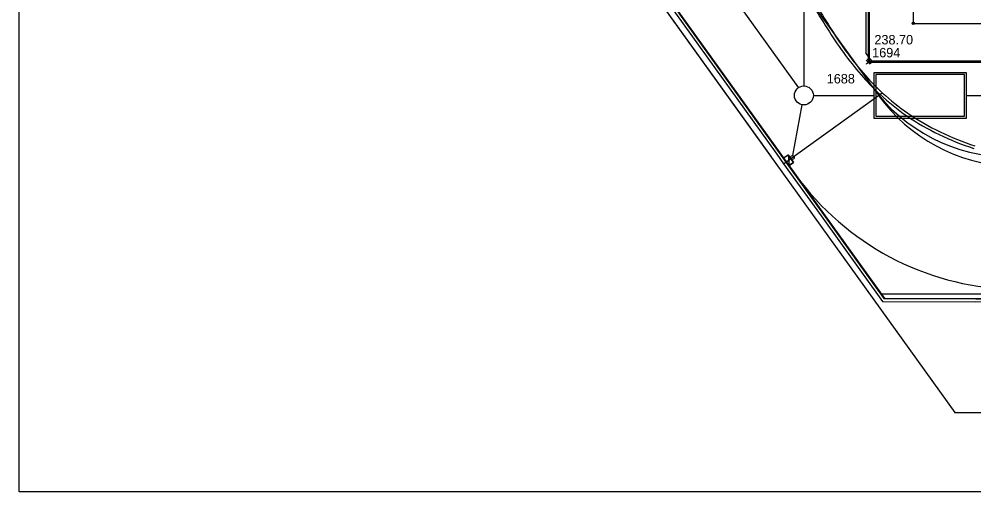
# Model space of a CAD drawing. Extents: x -264165 to -263733, y -1242319 to -1242245.
# Drawn here: x -264165.4 to -264114.9, y -1242319.2 to -1242294.2 of the extents above; entities that cross this region are included whole.
import ezdxf

# ---------------------------------------------------------------- set-up
doc = ezdxf.new("R2010")
doc.units = 0
for name, color, linetype in [('KFA_BOD_CISLO', 7, 'Continuous'), ('KFA_BOD_SYMBOL', 7, 'Continuous'), ('KFA_BOD_VYSKA', 7, 'Continuous'), ('KFA_SO_20-2_OBRUBNIKY_HORNA_HRANA', 7, 'Continuous'), ('PROJEKT_OBRUBNIKY_KOMUNIKACIE', 7, 'Continuous'), ('PROJEKT_TDZ_VODOROVNE', 7, 'Continuous'), ('RAM_NA_TLAC_1-250', 7, 'Continuous'), ('ROZHRANIE_SO_20-3_a_20-1', 7, 'Continuous'), ('SITUACIA_DSP_2D', 7, 'Continuous'), ('SO_20-1_OBRUBNIKY_DOLNA_HRANA', 7, 'Continuous'), ('SO_20-1_OBRUBNIKY_HORNA_HRANA', 7, 'Continuous'), ('SO_20-3_OBRUBNIKY_DOLNA_HRANA', 7, 'Continuous'), ('SO_20-3_OBRUBNIKY_HORNA_HRANA', 7, 'Continuous')]:
    doc.layers.add(name, color=color, linetype=linetype)

msp = doc.modelspace()

# ---------------------------------------------------------------- linework, layer by layer
at = {"layer": 'KFA_BOD_SYMBOL'}
for p, q in [((-264120.562, -1242296.59), (-264120.341, -1242296.369)), ((-264120.341, -1242296.59), (-264120.562, -1242296.369)), ((-264120.514, -1242296.541), (-264120.292, -1242296.319)), ((-264120.292, -1242296.541), (-264120.514, -1242296.319))]:
    msp.add_line(p, q, dxfattribs=at)
at = {"layer": 'KFA_SO_20-2_OBRUBNIKY_HORNA_HRANA'}
for points in [[(-264120.439, -1242271.461), (-264120.452, -1242296.479), (-264100.511, -1242296.484), (-264083.322, -1242296.485), (-264067.571, -1242296.478), (-264048.312, -1242296.489)], [(-264120.39, -1242271.447), (-264120.403, -1242296.43), (-264100.462, -1242296.435), (-264083.273, -1242296.436), (-264067.522, -1242296.429), (-264048.263, -1242296.44)]]:
    msp.add_lwpolyline(points, dxfattribs=at)
at = {"layer": 'PROJEKT_OBRUBNIKY_KOMUNIKACIE'}
for p, q in [((-264165.363, -1242245.312), (-264119.571, -1242308.982)), ((-264165.363, -1242246.168), (-264115.871, -1242314.982)), ((-264120.568, -1242296.035), (-264120.568, -1242271.189)), ((-264123.874, -1242292.722), (-264120.268, -1242297.737)), ((-264120.568, -1242296.035), (-264120.282, -1242296.432)), ((-264050.531, -1242308.982), (-264119.571, -1242308.982)), ((-264115.886, -1242314.982), (-264044.531, -1242314.982))]:
    msp.add_line(p, q, dxfattribs=at)
for points in [[(-264165.363, -1242246.168), (-264137.78, -1242284.52), (-264125.581, -1242301.482)], [(-263965.143, -1242296.432), (-264120.018, -1242296.432), (-264120.282, -1242296.432)]]:
    msp.add_lwpolyline(points, dxfattribs=at)
msp.add_arc((-264112.961, -1242292.482), 9, 215.724, 270, dxfattribs=at)
at = {"layer": 'PROJEKT_TDZ_VODOROVNE'}
for centre, radius, start, end in [((-264112.56, -1242292.924), 9.068, 215.874, 267.4682), ((-264112.435, -1242293.84), 14.642, 217.6201, 269.4957)]:
    msp.add_arc(centre, radius, start, end, dxfattribs=at)
at = {"layer": 'RAM_NA_TLAC_1-250'}
msp.add_lwpolyline([(-264165.363, -1242244.935), (-263732.863, -1242244.935), (-263732.863, -1242319.185), (-264165.363, -1242319.185)], close=True, dxfattribs=at)
at = {"layer": 'ROZHRANIE_SO_20-3_a_20-1'}
msp.add_line((-264124.926, -1242301.846), (-264119.708, -1242298.093), dxfattribs=at)
at = {"layer": 'SITUACIA_DSP_2D'}
for p, q in [((-264123.854, -1242244.935), (-264123.854, -1242297.736)), ((-264118.068, -1242244.935), (-264118.068, -1242294.432)), ((-264165.363, -1242245.312), (-264119.75, -1242308.732)), ((-264165.363, -1242246.168), (-264115.871, -1242314.982)), ((-264152.757, -1242258.05), (-264124.146, -1242297.83)), ((-264152.757, -1242258.05), (-264124.146, -1242297.83)), ((-264123.874, -1242292.722), (-264120.268, -1242297.737)), ((-264118.008, -1242294.432), (-264118.128, -1242294.432)), ((-264118.068, -1242294.492), (-264118.068, -1242294.372)), ((-264118.068, -1242294.432), (-264045.118, -1242294.432)), ((-264120.568, -1242296.035), (-264120.282, -1242296.432)), ((-264120.154, -1242297.036), (-264120.154, -1242299.436)), ((-264115.254, -1242297.036), (-264120.154, -1242297.036)), ((-264115.354, -1242297.136), (-264120.054, -1242297.136)), ((-264120.054, -1242297.136), (-264120.054, -1242299.336)), ((-264115.354, -1242299.336), (-264115.354, -1242297.136)), ((-264115.254, -1242299.436), (-264115.254, -1242297.036)), ((-264123.354, -1242298.236), (-264120.154, -1242298.236)), ((-264115.254, -1242298.236), (-264095.527, -1242298.236)), ((-264124.444, -1242301.414), (-264123.946, -1242298.728)), ((-264120.154, -1242299.436), (-264115.254, -1242299.436)), ((-264120.054, -1242299.336), (-264115.354, -1242299.336)), ((-264124.925, -1242301.537), (-264124.69, -1242301.368)), ((-264124.633, -1242301.943), (-264124.925, -1242301.537)), ((-264124.69, -1242301.368), (-264124.398, -1242301.774)), ((-264124.69, -1242301.368), (-264124.633, -1242301.943)), ((-264124.69, -1242301.368), (-264124.633, -1242301.943)), ((-264124.398, -1242301.774), (-264124.69, -1242301.368)), ((-264124.398, -1242301.774), (-264124.633, -1242301.943)), ((-264124.633, -1242301.943), (-264124.398, -1242301.774)), ((-264050.531, -1242308.732), (-264119.75, -1242308.732)), ((-264115.886, -1242314.982), (-264044.531, -1242314.982))]:
    msp.add_line(p, q, dxfattribs=at)
for points in [[(-264165.363, -1242246.168), (-264137.78, -1242284.52), (-264125.581, -1242301.482)], [(-264120.568, -1242296.035), (-264120.568, -1242271.189), (-264120.568, -1242271.189)], [(-263965.143, -1242296.432), (-264120.018, -1242296.432), (-264120.282, -1242296.432)]]:
    msp.add_lwpolyline(points, dxfattribs=at)
for centre, radius in [((-264118.068, -1242294.432), 0.06), ((-264123.854, -1242298.236), 0.5), ((-264124.462, -1242301.513), 0.1)]:
    msp.add_circle(centre, radius, dxfattribs=at)
msp.add_arc((-264112.961, -1242292.482), 9, 215.724, 270, dxfattribs=at)
at = {"layer": 'SO_20-1_OBRUBNIKY_DOLNA_HRANA'}
msp.add_lwpolyline([(-264124.808, -1242301.762), (-264122.825, -1242304.519), (-264119.622, -1242308.973), (-264114.767, -1242308.991), (-264107.775, -1242308.984), (-264100.725, -1242308.982), (-264086.721, -1242308.982)], dxfattribs=at)
for centre, major_axis, ratio, start_param, end_param in [((-264108.973, -1242286.088), (13.129, -10.761), 0.957198, 4.669399, 4.776308), ((-264110.494, -1242287.503), (-7.141, -12.3), 0.999902, 6.218556, 6.497029)]:
    msp.add_ellipse(centre, major_axis=major_axis, ratio=ratio, start_param=start_param, end_param=end_param, dxfattribs=at)
at = {"layer": 'SO_20-1_OBRUBNIKY_HORNA_HRANA'}
msp.add_lwpolyline([(-264124.926, -1242301.846), (-264122.945, -1242304.592), (-264119.692, -1242309.125), (-264114.755, -1242309.139), (-264107.766, -1242309.132), (-264100.735, -1242309.134), (-264093.764, -1242309.133), (-264086.73, -1242309.126)], dxfattribs=at)
for centre, major_axis, ratio, start_param, end_param in [((-264109.865, -1242287.203), (11.619, -9.556), 0.975712, 4.666867, 4.782223), ((-264110.586, -1242287.673), (-7.289, -11.816), 0.999902, 6.242047, 6.527042)]:
    msp.add_ellipse(centre, major_axis=major_axis, ratio=ratio, start_param=start_param, end_param=end_param, dxfattribs=at)
at = {"layer": 'SO_20-3_OBRUBNIKY_DOLNA_HRANA'}
msp.add_lwpolyline([(-264165.363, -1242245.338), (-264164.83, -1242246.079), (-264158.406, -1242254.997), (-264151.981, -1242263.929), (-264145.549, -1242272.885), (-264139.496, -1242281.305), (-264132.148, -1242291.541), (-264125.165, -1242301.265), (-264124.808, -1242301.762)], dxfattribs=at)
for centre, major_axis, ratio, start_param, end_param in [((-263998.852, -1242215.853), (84.302, -140.139), 0.897217, 4.7183, 4.736655), ((-264106.585, -1242284.92), (11.187, -15.171), 0.995879, 4.635852, 4.796229), ((-264110.944, -1242288.545), (9.2, -9.413), 0.995723, 4.669382, 4.764177)]:
    msp.add_ellipse(centre, major_axis=major_axis, ratio=ratio, start_param=start_param, end_param=end_param, dxfattribs=at)
at = {"layer": 'SO_20-3_OBRUBNIKY_HORNA_HRANA'}
msp.add_lwpolyline([(-264165.363, -1242245.587), (-264164.951, -1242246.159), (-264158.525, -1242255.075), (-264152.106, -1242264.005), (-264145.671, -1242272.964), (-264139.631, -1242281.361), (-264132.272, -1242291.613), (-264125.285, -1242301.347), (-264124.926, -1242301.846)], dxfattribs=at)
for centre, major_axis, ratio, start_param, end_param in [((-264058.218, -1242251.717), (75.932, -123.334), 0.533241, 4.712594, 4.733384), ((-264107.502, -1242285.613), (10.173, -14.289), 0.99631, 4.646606, 4.817168), ((-264111.21, -1242288.87), (8.289, -9.444), 0.998043, 4.717107, 4.818155)]:
    msp.add_ellipse(centre, major_axis=major_axis, ratio=ratio, start_param=start_param, end_param=end_param, dxfattribs=at)

# ---------------------------------------------------------------- texts
at = {"layer": 'KFA_BOD_CISLO'}
for s, p in [('1694', (-264120.243, -1242296.224)), ('1688', (-264122.645, -1242297.601))]:
    msp.add_text(s, height=0.5, dxfattribs=at).set_placement(p)
at = {"layer": 'KFA_BOD_VYSKA'}
msp.add_text('238.70', height=0.5, dxfattribs=at).set_placement((-264120.124, -1242295.54))

doc.saveas('drawing.dxf')
